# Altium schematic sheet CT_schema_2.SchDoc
size 357 x 214 mm
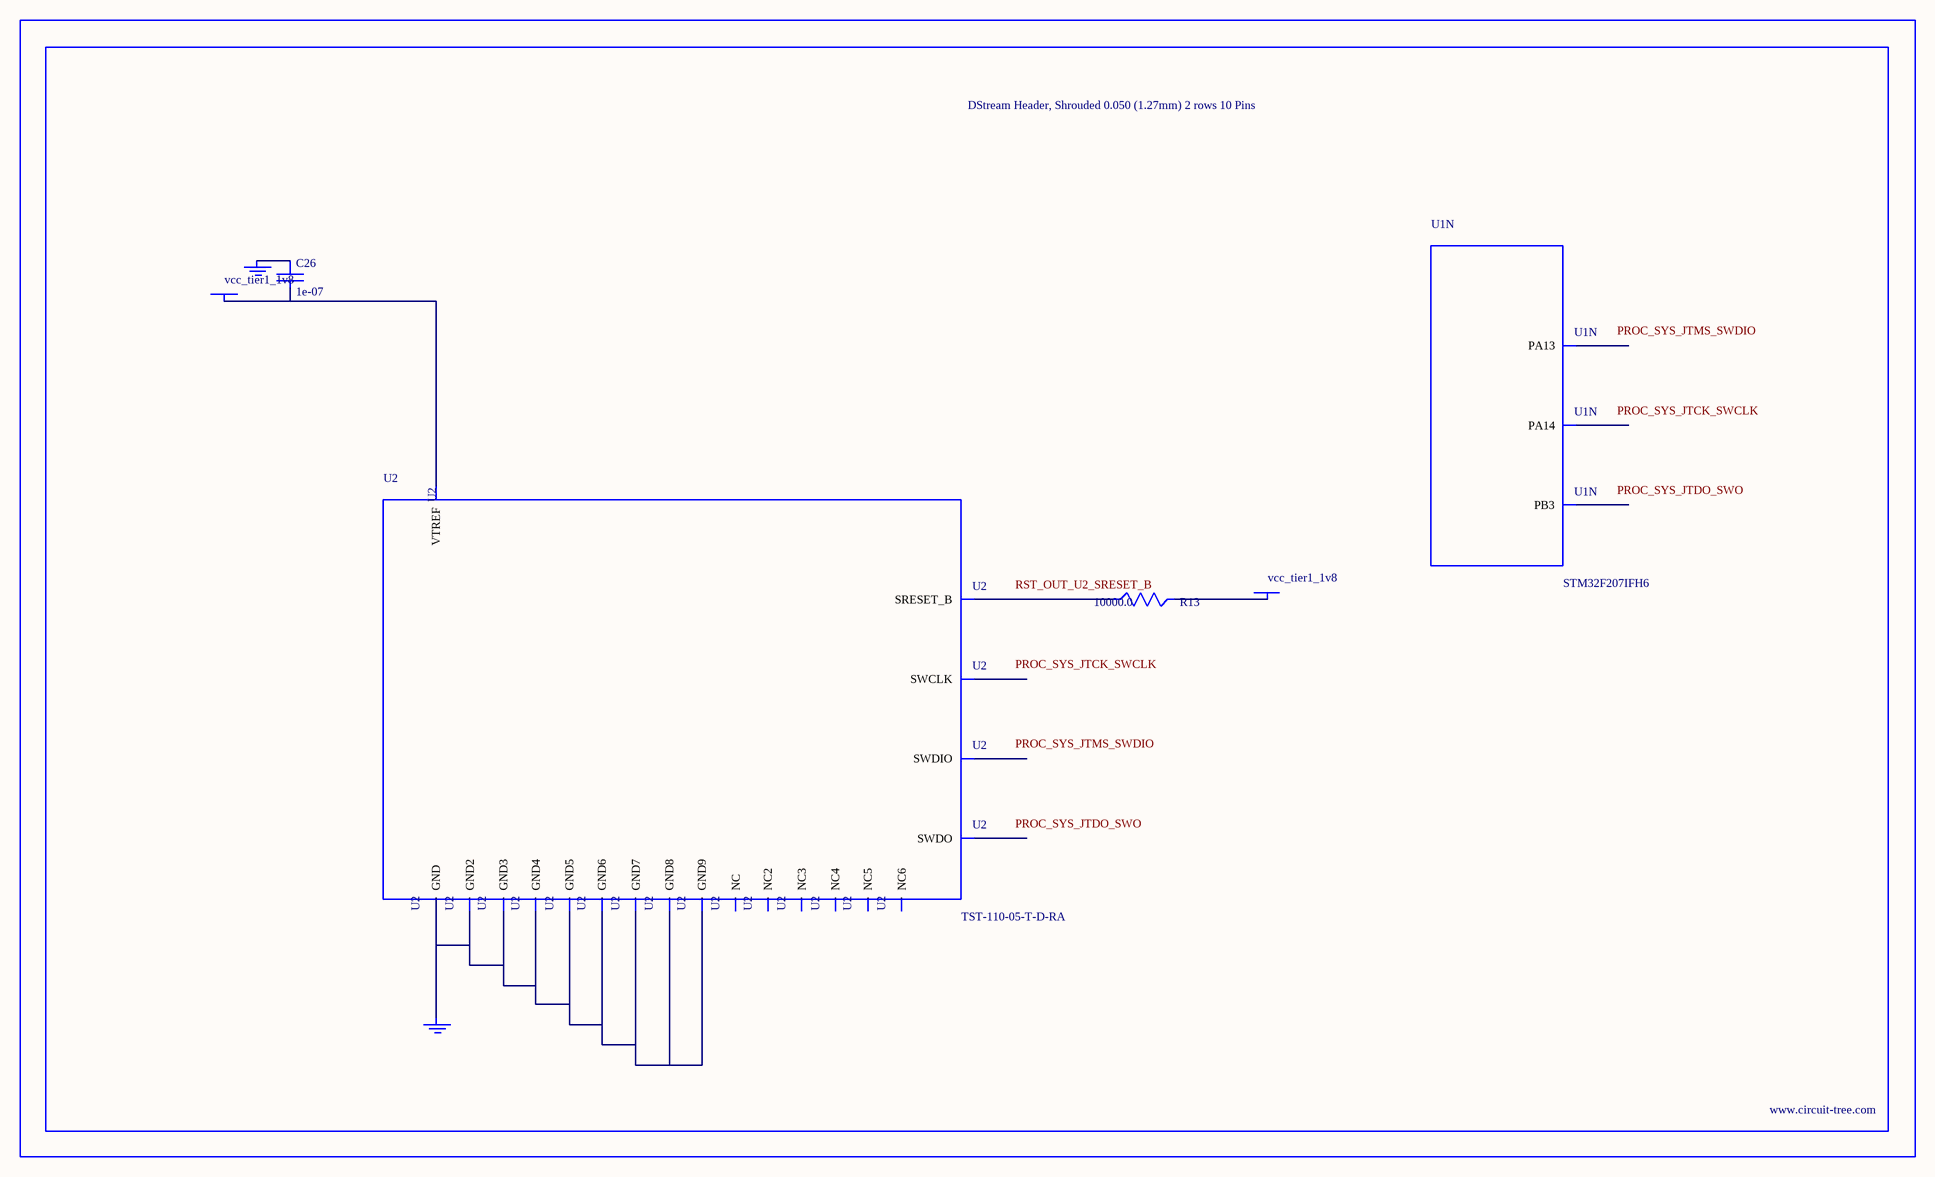
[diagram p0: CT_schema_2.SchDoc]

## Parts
BORDER1  (no value)
C26  1e-07  [C0402]
GND_INSTANCE_1_0  (no value)
GND_INSTANCE_1_1  (no value)
POWER_INSTANCE_1_0  vcc_tier1_1v8
POWER_INSTANCE_1_1  vcc_tier1_1v8
R13  10000.0  [R0603]
U1  STM32F207IFH6  [UFBGA176_25]  (part N of 16)
U2  TST-110-05-T-D-RA  [TST-110-05-T-D-RA]

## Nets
NetC26_1: C26.1 GND_INSTANCE_1_0.0(GND)
NetC26_2: C26.2 POWER_INSTANCE_1_0.0(PWR) U2.1(VTREF)
NetGND_INSTANCE_1_1_0: GND_INSTANCE_1_1.0(GND) U2.4(GND) U2.6(GND2) U2.8(GND3) U2.10(GND4) U2.12(GND5) U2.14(GND6) U2.16(GND7) U2.18(GND8) U2.20(GND9)
NetPOWER_INSTANCE_1_1_0: POWER_INSTANCE_1_1.0(PWR) R13.2
NetR13_1: R13.1 U2.15(SRESET_B)

Not connected (* = marked no-connect by the designer): U1 A10(PB3) A14(PA14) A15(PA13); U2 2(NC) 3(NC2) 5(NC3) 7(SWDIO) 9(SWCLK) 11(NC4) 13(SWDO) 17(NC5) 19(NC6)

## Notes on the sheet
- Labels drawn without touching a wire or pin: PROC_SYS_JTCK_SWCLK, PROC_SYS_JTDO_SWO, PROC_SYS_JTMS_SWDIO, RST_OUT_U2_SRESET_B

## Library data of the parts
BORDER1 = BORDER_PAGE1
C26 = C0402C104K3RACTU
GND_INSTANCE_1_0 GND_INSTANCE_1_1 = GND
POWER_INSTANCE_1_0 POWER_INSTANCE_1_1 = PWR
R13 = RC0603JR-0710KL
